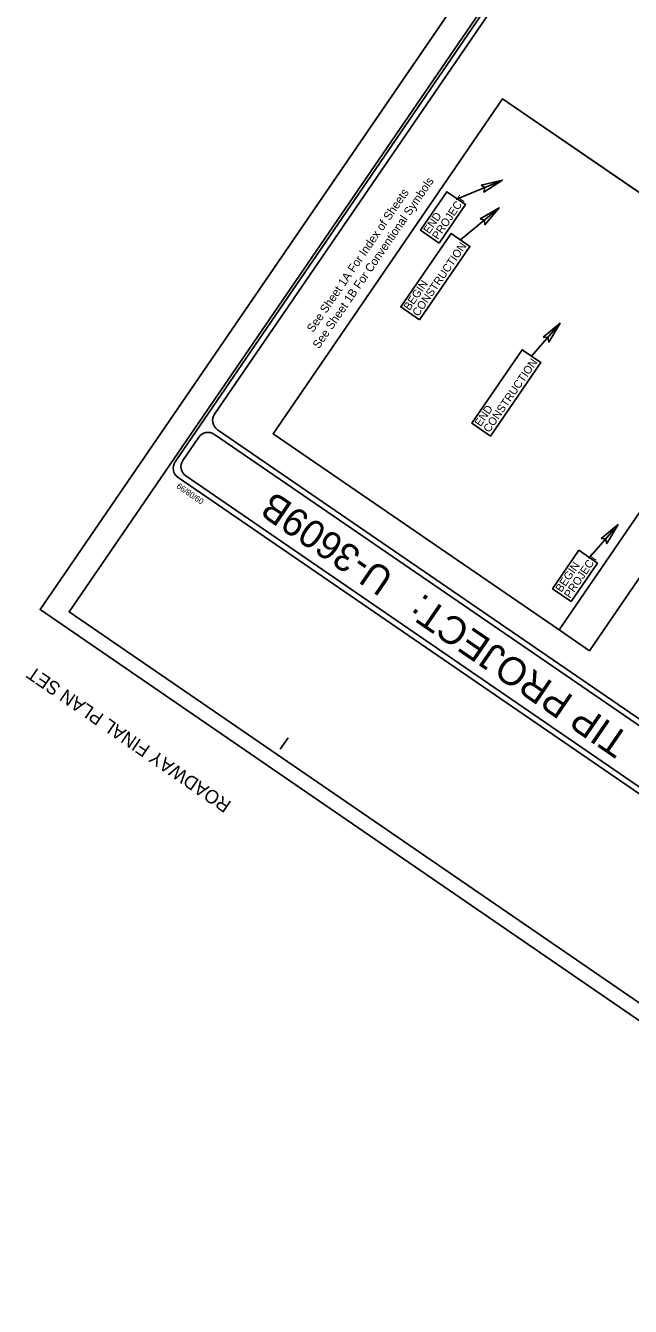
# Model space of a CAD drawing. Extents: x 2312641 to 2338852, y 590461 to 618614.
# Drawn here: x 2312641 to 2320204, y 590461 to 606464 of the extents above; entities that cross this region are included whole.
import ezdxf

# ---------------------------------------------------------------- set-up
doc = ezdxf.new("R2010")
doc.units = 0
for name, color, linetype in [('Exist Other Culture Sign Post Text', 7, 'Continuous'), ('Exist Property Iron Pin Cogo Number', 7, 'Continuous'), ('Exist Property Monument Cogo Number', 7, 'Continuous'), ('Exist Structure Minor Pipes RCP 15 Inch', 7, 'Continuous'), ('Exist Utilities Power Joint Use Telephone CELL', 7, 'Continuous'), ('Exist Utilities Power Joint Use Telephone Text', 7, 'Continuous')]:
    doc.layers.add(name, color=color, linetype=linetype)

msp = doc.modelspace()

# ---------------------------------------------------------------- linework, layer by layer
at = {"layer": 'Exist Other Culture Sign Post Text'}
for q in [(2326149, 618614), (2325524, 590461)]:
    msp.add_line((2312821, 599167), q, dxfattribs=at)
at = {"layer": 'Exist Property Iron Pin Cogo Number'}
for p, q in [((2324683, 594806), (2315040, 601414)), ((2326780, 593284), (2315001, 601356)), ((2315826, 597422), (2315925, 597566)), ((2315826, 597422), (2315925, 597566))]:
    msp.add_line(p, q, dxfattribs=at)
for points in [[(2326224, 618105), (2314511, 601013)], [(2326242, 618007), (2315004, 601609)], [(2314806, 601320), (2314608, 601031)], [(2314547, 600819), (2326442, 592667)], [(2314547, 600819), (2326442, 592667)], [(2314645, 600837), (2326424, 592764)]]:
    msp.add_lwpolyline(points, dxfattribs=at)
for points in [[(2315736, 601364), (2318606, 605551), (2322182, 603100), (2319312, 598913)], [(2322182, 603100), (2319312, 598913), (2319691, 598653), (2322561, 602841)]]:
    msp.add_lwpolyline(points, close=True, dxfattribs=at)
for centre, start, end in [((2315119, 601530), 145.5761, 235.5761), ((2314921, 601241), 55.5761, 145.5761), ((2314626, 600934), 145.5761, 235.5761), ((2314723, 600953), 145.5761, 235.5761)]:
    msp.add_arc(centre, 140, start, end, dxfattribs=at)
at = {"layer": 'Exist Property Monument Cogo Number'}
msp.add_lwpolyline([(2321956, 602771), (2319312, 598913), (2315736, 601364), (2318606, 605551), (2321083, 603853), (2320857, 603523)], dxfattribs=at)
at = {"layer": 'Exist Structure Minor Pipes RCP 15 Inch'}
for p, q in [((2318040, 604298), (2318604, 604533)), ((2318079, 603786), (2318563, 604186)), ((2318967, 602335), (2319325, 602746)), ((2319691, 599818), (2320050, 600229))]:
    msp.add_line(p, q, dxfattribs=at)
for points in [[(2318337, 604472), (2318604, 604533), (2318372, 604384), (2318385, 604442)], [(2317813, 603747), (2318143, 604227), (2317908, 604388), (2317579, 603908)], [(2318325, 604050), (2318563, 604186), (2318384, 603976), (2318380, 604035)], [(2317567, 602788), (2318196, 603706), (2317961, 603867), (2317332, 602949)], [(2319113, 602573), (2319325, 602746), (2319183, 602510), (2319170, 602568)], [(2318455, 601336), (2319084, 602254), (2318849, 602415), (2318220, 601497)], [(2319838, 600056), (2320050, 600229), (2319908, 599993), (2319894, 600051)], [(2319465, 599267), (2319794, 599747), (2319559, 599908), (2319230, 599428)]]:
    msp.add_lwpolyline(points, close=True, dxfattribs=at)
at = {"layer": 'Exist Utilities Power Joint Use Telephone CELL'}
msp.add_lwpolyline([(2326149, 618614), (2312821, 599167), (2325524, 590461), (2338852, 609909)], close=True, dxfattribs=at)
at = {"layer": 'Exist Utilities Power Joint Use Telephone Text'}
msp.add_lwpolyline([(2325368, 590789), (2338557, 610034), (2326373, 618385), (2313184, 599139)], close=True, dxfattribs=at)

# ---------------------------------------------------------------- texts
at = {"layer": 'Exist Property Iron Pin Cogo Number'}
for s, height, rotation, p in [('See Sheet 1B For Conventional Symbols', 105, 55.5761, (2316308, 602418)), ('See Sheet 1A For Index of Sheets', 105, 55.5761, (2316235, 602623)), ('09/08/99', 73.5, 145.5761, (2314878, 600537)), ('U-3609B', 350, 145.5761, (2317266, 599611)), ('TIP PROJECT:', 350, 145.5761, (2320217, 597588)), ('ROADWAY FINAL PLAN SET', 168.75, 145.5761, (2315225, 596758))]:
    msp.add_text(s, height=height, rotation=rotation, dxfattribs=at).set_placement(p)
at = {"layer": 'Exist Structure Minor Pipes RCP 15 Inch'}
for s, p in [('PROJECT', (2317797, 603782)), ('END', (2317689, 603856)), ('CONSTRUCTION', (2317551, 602823)), ('BEGIN', (2317442, 602897)), ('CONSTRUCTION', (2318438, 601371)), ('END', (2318330, 601446)), ('PROJECT', (2319448, 599302)), ('BEGIN', (2319340, 599376))]:
    msp.add_text(s, height=100, rotation=55.5761, dxfattribs=at).set_placement(p)

doc.saveas('drawing.dxf')
